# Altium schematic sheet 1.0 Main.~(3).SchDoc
size A4; SheetNumber: 1; SheetTotal: 1
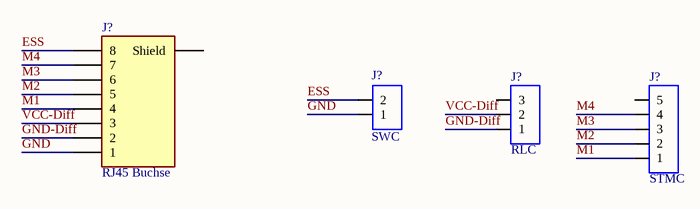
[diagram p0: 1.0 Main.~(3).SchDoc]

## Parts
(Parts that share a designator on the sheet are numbered #1, #2 ... from top to bottom, then left to right.)
J?#1  RJ45 Buchse  [J_TE-RJ45-8L-B]
J?#2  SWC  [SIP-2]
J?#3  RLC  [Sip-3]
J?#4  STMC  [SIP-5]

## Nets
ESS: J?#1.8 J?#2.2
GND: J?#1.1 J?#2.1
GND-Diff: J?#1.2 J?#3.1
M1: J?#1.4 J?#4.1
M2: J?#1.5 J?#4.2
M3: J?#1.6 J?#4.3
M4: J?#1.7 J?#4.4
VCC-Diff: J?#1.3 J?#3.2

Not connected (* = marked no-connect by the designer): J?#1 MP(Shield); J?#3 3; J?#4 5

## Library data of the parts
J?#1 = J_RJ45: Connector
J?#2 = J_THT_CON2: Stecker
J?#3 = J_THT_CON3: Stecker
J?#4 = J_THT_CON5: Stecker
